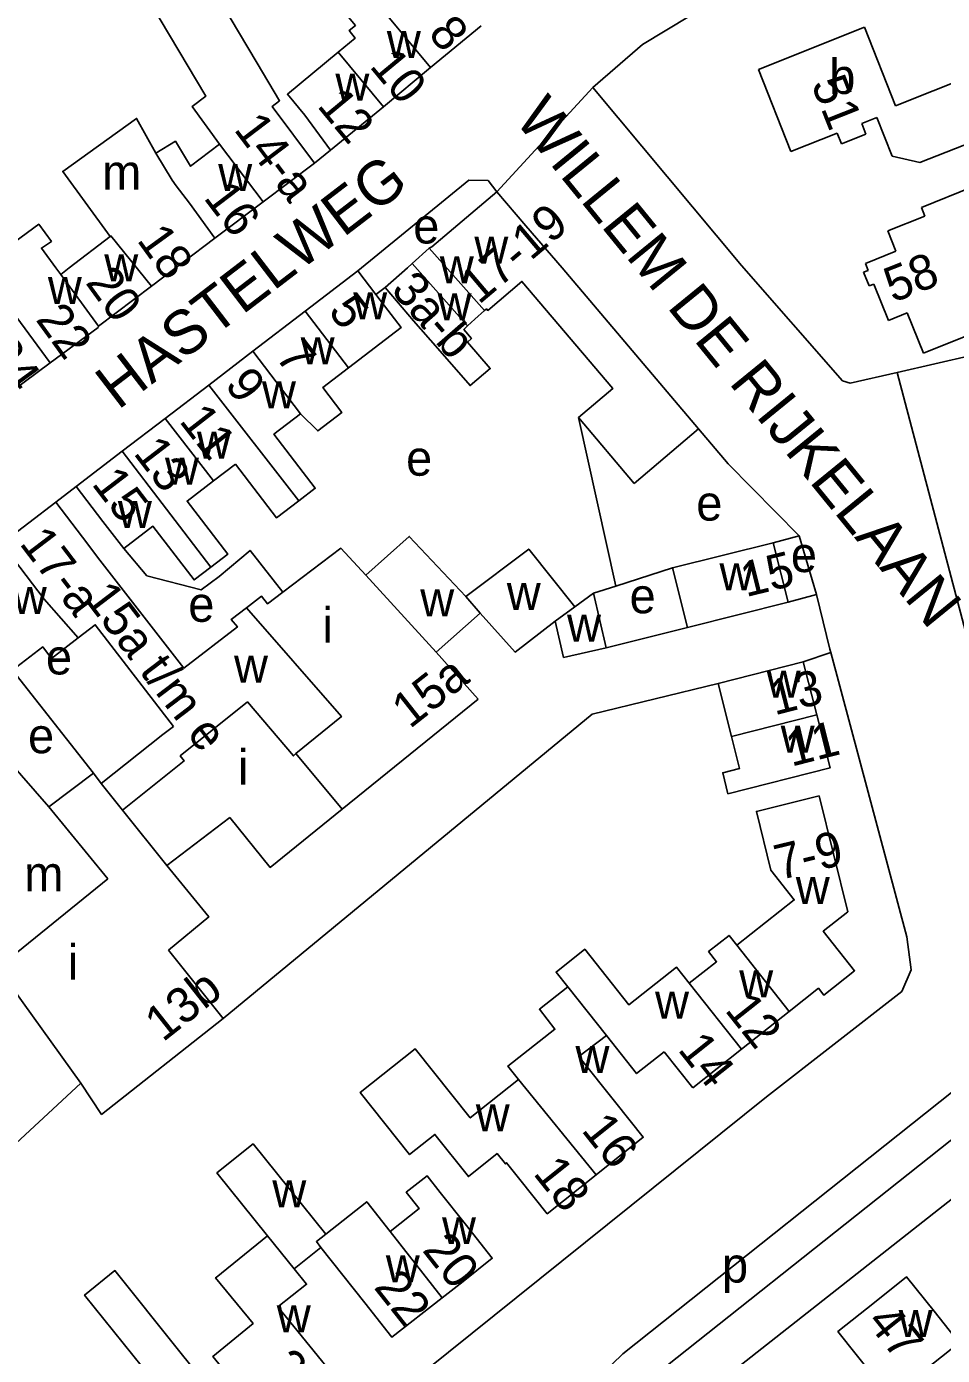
# Model space of a CAD drawing. Extents: x 159261 to 160849, y 382514 to 384534.
# Drawn here: x 159903.5 to 160007.7, y 383126.2 to 383277.5 of the extents above; entities that cross this region are included whole.
import ezdxf

# ---------------------------------------------------------------- set-up
doc = ezdxf.new("R2010")
doc.units = 0
for name, color, linetype in [('BLT_Basislijn', 7, 'Continuous'), ('BLT_Bebouwing', 7, 'Continuous'), ('BLT_Centroide', 7, 'Continuous'), ('BLT_Huisnummer', 7, 'Continuous'), ('BLT_Huisnummer_ tussenligend', 7, 'Continuous'), ('BLT_Huisnummer_reeks', 7, 'Continuous'), ('BLT_Onderdoorgang_en_onderverdeling', 7, 'Continuous'), ('BLT_Onderverdeling_panden', 7, 'Continuous'), ('BLT_Straatnaam', 7, 'Continuous'), ('BLT_Vlakafsluiter', 7, 'Continuous')]:
    doc.layers.add(name, color=color, linetype=linetype)

msp = doc.modelspace()

# ---------------------------------------------------------------- linework, layer by layer
at = {"layer": 'BLT_Basislijn'}
for p, q in [((159938.07, 383263.39), (159936.26, 383261.89)), ((159944.29, 383247.75), (159943.26, 383246.96)), ((160002.6, 383238.09), (160025.24, 383243.27)), ((159966.33, 383232.94), (159970.55, 383213.76)), ((159983.35, 383227.69), (159979.99, 383231.67)), ((159991.43, 383219.48), (159983.35, 383227.69)), ((159909.14, 383225.09), (159906.81, 383223.3)), ((159988.48, 383218.69), (159991.43, 383219.48)), ((159991.43, 383219.48), (159993.39, 383212.81)), ((159970.55, 383213.76), (159977.03, 383215.85)), ((159968.04, 383212.95), (159970.55, 383213.76)), ((159990.18, 383211.92), (159993.39, 383212.81)), ((159969.48, 383206.74), (159978.71, 383209.07)), ((159995.04, 383206.22), (159991.89, 383205.14)), ((159911.09, 383192.48), (159901.9, 383204.21)), ((159982.2, 383202.68), (159967.86, 383199.17)), ((159967.86, 383199.17), (159925.85, 383164.55))]:
    msp.add_line(p, q, dxfattribs=at)
for points in [[(160021.41, 383277.29), (160018.22, 383282.44), (159994.78, 383283.13), (159987.36, 383281.93), (159981.98, 383280.04), (159978.94, 383278.62), (159973.6, 383275.4), (159967.95, 383270.52)], [(159967.95, 383270.52), (159984.86, 383250.25), (159996.37, 383237.12), (159997.23, 383236.88), (160002.6, 383238.09)], [(159957.03, 383258.66), (159956.02, 383259.94), (159953.82, 383259.98), (159941.2, 383249.65)], [(160054.36, 383179.01), (160032.76, 383162.37), (160030.21, 383161.85), (160029.07, 383162.12), (160027.8, 383163.23), (160019.12, 383175.15), (160018.49, 383176.44), (160012.33, 383201.12), (160002.6, 383238.09)], [(159914.55, 383218.03), (159917.19, 383214.95), (159923.35, 383213.32), (159925.4, 383214.85), (159928.92, 383217.82), (159932.64, 383213.07)], [(159995.04, 383206.22), (159994.94, 383206.6), (159993.39, 383212.81)], [(159824, 383048.2), (159832.93, 383036.19), (159835.32, 383035.09), (159837.88, 383035.36), (159987.71, 383155.63), (160003.12, 383167.63), (160004.17, 383170.08), (160003.69, 383173.83), (159995.04, 383206.22)], [(159966.71, 383117.34), (159966.48, 383118.05), (159966.76, 383121.08), (159967.66, 383122.77), (159971.37, 383126.36), (160008.97, 383156.27)], [(160008.97, 383156.27), (160011.01, 383153.22), (160010.66, 383152.37), (160009.9, 383151.65), (159966.71, 383117.34)], [(160036.51, 383129.07), (160018.22, 383147.31), (160016.68, 383148.32), (160014.86, 383148.36), (160012.99, 383147.28), (159982.57, 383123.36), (159972.05, 383114.68), (159968.6, 383112.35)]]:
    msp.add_lwpolyline(points, dxfattribs=at)
at = {"layer": 'BLT_Bebouwing'}
for p, q in [((159955.25, 383277.53), (159949.46, 383272.79)), ((159986.81, 383272.58), (159998.88, 383277.37)), ((159998.88, 383277.37), (160002.41, 383268.44)), ((159949.46, 383272.79), (159944.11, 383268.3)), ((159990.5, 383263.23), (159986.81, 383272.58)), ((160002.41, 383268.44), (160010.96, 383271.83)), ((159944.11, 383268.3), (159938.07, 383263.39)), ((160000.28, 383267.11), (159998.56, 383266.43)), ((159998.56, 383266.43), (159999.04, 383265.21)), ((160002.02, 383262.71), (160000.28, 383267.11)), ((159995.77, 383265.32), (159990.5, 383263.23)), ((159996.25, 383264.11), (159995.77, 383265.32)), ((159999.04, 383265.21), (159996.25, 383264.11)), ((160013.55, 383265.3), (160005.18, 383261.99)), ((159930.43, 383257.51), (159936.26, 383261.89)), ((160005.18, 383261.99), (160002.02, 383262.71)), ((159949.63, 383252.38), (159957.03, 383258.66)), ((159957.03, 383258.66), (159960.32, 383254.78)), ((160005.35, 383256.86), (160011.26, 383259.24)), ((159924.93, 383253.37), (159930.43, 383257.51)), ((160005.73, 383255.89), (160005.35, 383256.86)), ((160001.52, 383254.19), (160005.73, 383255.89)), ((159960.32, 383254.78), (159964.46, 383250)), ((160002.45, 383251.87), (160001.52, 383254.19)), ((159913, 383253.57), (159908.34, 383249.98)), ((159917.72, 383247.9), (159924.93, 383253.37)), ((159949.32, 383252.21), (159949.63, 383252.38)), ((159947.38, 383250.48), (159949.32, 383252.21)), ((159998.99, 383250.47), (160002.45, 383251.87)), ((159907.38, 383249.23), (159906.8, 383250)), ((159908.34, 383249.98), (159907.38, 383249.23)), ((159935.21, 383245.06), (159941.2, 383249.65)), ((159941.2, 383249.65), (159943.26, 383246.96)), ((159944.29, 383247.75), (159946.83, 383250)), ((159947.38, 383250.48), (159946.83, 383250)), ((159964.46, 383250), (159979.99, 383231.67)), ((159998.75, 383249.48), (159999.3, 383249.69)), ((159999.39, 383247.93), (159998.75, 383249.48)), ((159999.3, 383249.69), (159998.99, 383250.47)), ((159917.72, 383247.9), (159911.69, 383243.35)), ((159999.92, 383248.14), (159999.39, 383247.93)), ((160001.59, 383243.99), (159999.92, 383248.14)), ((159929.24, 383240.49), (159935.21, 383245.06)), ((159954.51, 383244.14), (159955.61, 383245.12)), ((160003.74, 383244.85), (160001.59, 383243.99)), ((160005.57, 383240.28), (160003.74, 383244.85)), ((159953.67, 383243.39), (159954.51, 383244.14)), ((160011.58, 383242.67), (160005.57, 383240.28)), ((159924.23, 383236.65), (159929.24, 383240.49)), ((159906.18, 383239.17), (159899.9, 383234.52)), ((159919.25, 383232.84), (159924.23, 383236.65)), ((159914.38, 383229.11), (159919.25, 383232.84)), ((159909.14, 383225.09), (159914.38, 383229.11)), ((159924.75, 383225.74), (159927.25, 383227.65)), ((159900.65, 383218.62), (159906.81, 383223.3)), ((159988.48, 383218.69), (159977.03, 383215.85)), ((159990.18, 383211.92), (159988.48, 383218.69)), ((159977.03, 383215.85), (159978.71, 383209.07)), ((159968.04, 383212.95), (159969.48, 383206.74)), ((159978.71, 383209.07), (159990.18, 383211.92)), ((159955.13, 383210.7), (159950.12, 383206.24)), ((159950.12, 383206.24), (159954.89, 383200.88)), ((159969.48, 383206.74), (159964.61, 383205.62)), ((159982.2, 383202.68), (159991.89, 383205.14)), ((159991.89, 383205.14), (159993.43, 383199.11)), ((159919, 383196.87), (159920.2, 383197.77)), ((159906.03, 383188.63), (159911.09, 383192.48)), ((159926.64, 383187.42), (159919.45, 383181.97)), ((159919.63, 383172.32), (159925.85, 383164.55)), ((159990.3, 383165.36), (159984.87, 383161.05)), ((159984.87, 383161.05), (159979.32, 383156.66)), ((159895.84, 383144.46), (159909.68, 383157.19)), ((159937, 383138.49), (159933.93, 383136.07))]:
    msp.add_line(p, q, dxfattribs=at)
for points in [[(159936.26, 383261.89), (159931.45, 383268.36), (159932.29, 383269), (159929.73, 383273.29), (159916.39, 383295.73), (159913.84, 383300.03)], [(159907.88, 383296.49), (159910.43, 383292.19), (159923.9, 383269.54), (159922.33, 383268.34), (159925.46, 383264.06)], [(159940.92, 383286.67), (159937.99, 383284.83), (159940.32, 383280.95), (159940.69, 383280.51), (159939.39, 383279.43), (159940.91, 383277.59), (159940.2, 383276.99), (159940.9, 383276.14), (159938.95, 383274.53)], [(159938.07, 383263.39), (159935.15, 383267.37), (159933.18, 383269.74), (159938.95, 383274.53)], [(159918.2, 383263.04), (159916.01, 383267), (159911.67, 383263.89), (159907.61, 383260.97), (159913, 383253.57)], [(159925.46, 383264.06), (159922.15, 383261.55), (159920.43, 383264.39), (159918.2, 383263.04)], [(159906.8, 383250), (159905.18, 383252.23), (159906.31, 383252.99), (159904.87, 383254.95), (159898.64, 383250.39), (159902.3, 383245.4), (159901.86, 383245.07)], [(159955.61, 383245.12), (159955.84, 383245.32), (159955.98, 383245.15), (159959.88, 383248.45), (159970.22, 383236.24), (159966.33, 383232.94)], [(159943.26, 383246.96), (159944.24, 383245.68), (159946.12, 383243.18), (159940.15, 383238.61)], [(159953.67, 383243.39), (159953.28, 383242.96), (159954.13, 383241.95), (159953.68, 383241.54), (159956.26, 383238.53), (159953.97, 383236.58), (159950.31, 383240.79), (159947.54, 383243.95), (159944.29, 383247.75)], [(159911.69, 383243.35), (159911.64, 383243.21), (159906.18, 383239.17)], [(159934.68, 383233.37), (159936.63, 383231.42), (159939.39, 383233.54), (159937.22, 383236.37), (159940.15, 383238.61)], [(159934.48, 383223.48), (159936.34, 383224.9), (159931.64, 383231.04), (159934.68, 383233.37)], [(159966.33, 383232.94), (159972.66, 383225.46)], [(159972.66, 383225.46), (159976.17, 383228.44), (159979.99, 383231.67)], [(159927.25, 383227.65), (159931.94, 383221.53), (159934.48, 383223.48)], [(159914.55, 383218.03), (159912.18, 383221.12), (159909.14, 383225.09)], [(159924.47, 383215.92), (159926.39, 383217.38), (159921.75, 383223.44), (159924.75, 383225.74)], [(159906.81, 383223.3), (159909.84, 383219.33), (159911.81, 383216.73)], [(159914.55, 383218.03), (159917.87, 383220.58), (159922.56, 383214.46), (159924.47, 383215.92)], [(159942.11, 383214.99), (159947.04, 383219.41), (159953.5, 383212.59)], [(159932.64, 383213.07), (159939.27, 383218.08), (159942.11, 383214.99)], [(159953.5, 383212.59), (159960.65, 383217.97), (159965.9, 383211.4)], [(159928.51, 383211.3), (159926.78, 383209.97), (159927.49, 383209.12), (159921.39, 383204.41), (159911.81, 383216.73)], [(159928.51, 383211.3), (159930.22, 383212.62), (159930.9, 383211.75), (159932.64, 383213.07)], [(159965.9, 383211.4), (159968.04, 383212.95)], [(159963.65, 383209.76), (159959.09, 383206.26), (159955.13, 383210.7)], [(159909.34, 383207.86), (159911.3, 383209.36), (159920.2, 383197.77)], [(159964.61, 383205.62), (159963.65, 383209.76)], [(159901.9, 383204.21), (159905.33, 383206.84), (159906.33, 383205.54), (159909.34, 383207.86)], [(159983.73, 383196.65), (159982.2, 383202.68)], [(159954.89, 383200.88), (159939.41, 383188.37)], [(159983.73, 383196.65), (159984.66, 383193.01), (159982.73, 383192.52), (159983.32, 383190.12), (159994.98, 383193.08), (159993.43, 383199.11)], [(159911.99, 383191.29), (159919, 383196.87)], [(159901.35, 383194), (159906.03, 383188.63)], [(159911.09, 383192.48), (159911.99, 383191.29)], [(159990.3, 383165.36), (159993.62, 383167.99), (159994.23, 383167.22), (159997.74, 383169.99), (159994.18, 383174.48), (159996.97, 383176.69), (159993.71, 383189.89), (159988.86, 383188.69), (159986.56, 383188.12), (159988.21, 383181.42), (159990.88, 383178.05), (159984.35, 383172.88)], [(159939.41, 383188.37), (159931.22, 383181.75), (159926.64, 383187.42)], [(159919.45, 383181.97), (159924.22, 383176.11), (159919.63, 383172.32)], [(159984.35, 383172.88), (159983.46, 383174), (159981.12, 383172.16), (159982.03, 383171.01), (159978.92, 383168.55)], [(159965.11, 383168.14), (159963.76, 383169.83), (159967.03, 383172.42), (159972.05, 383166.1), (159977.47, 383170.39), (159978.92, 383168.55)], [(159965.11, 383168.14), (159961.86, 383165.59), (159963.63, 383163.33), (159958.27, 383159.13), (159959.49, 383157.61)], [(159909.68, 383157.19), (159912.02, 383153.63), (159925.85, 383164.55)], [(159968.32, 383146.75), (159973.68, 383151.03), (159970.56, 383154.94), (159966.37, 383160.21), (159969.52, 383162.6)], [(159976.07, 383160.77), (159972.93, 383158.28), (159969.52, 383162.6)], [(159968.32, 383146.75), (159962.75, 383142.32), (159959.64, 383146.23), (159958.13, 383148.12), (159957.99, 383148), (159957.05, 383149.17), (159953.78, 383146.56), (159949.96, 383151.36), (159947.08, 383149.06), (159941.46, 383156.12), (159947.71, 383161.1), (159953.99, 383153.23), (159959.49, 383157.61)], [(159979.32, 383156.66), (159976.07, 383160.77)], [(159930.93, 383139.8), (159925.16, 383146.97), (159929.27, 383150.28), (159937.55, 383140)], [(159944.88, 383140.31), (159948.17, 383142.91), (159946.7, 383144.77), (159949.08, 383146.65), (159950.58, 383144.74), (159953.4, 383141.18), (159956.5, 383137.25), (159953.17, 383134.62), (159950.79, 383132.77)], [(159937.55, 383140), (159942.21, 383143.68), (159944.88, 383140.31)], [(159932.07, 383131.72), (159935.72, 383127.24), (159938.88, 383123.38), (159932.63, 383118.27), (159929.44, 383122.18), (159927.52, 383124.53), (159926.59, 383123.77), (159924.69, 383126.09), (159929.27, 383129.83), (159925.01, 383135.04), (159925.05, 383135.07), (159930.93, 383139.8)], [(159950.79, 383132.77), (159945.08, 383128.26), (159941.98, 383132.18), (159937, 383138.49)], [(159916.89, 383112.17), (159919.71, 383108.67), (159925.93, 383113.69), (159920.63, 383120.27), (159923.9, 383122.91), (159920.78, 383126.81), (159913.55, 383135.86), (159910.08, 383133.06), (159918.9, 383122.12), (159912.82, 383117.22), (159916.89, 383112.17)], [(159933.93, 383136.07), (159935.36, 383134.3), (159932.07, 383131.72)], [(160006.79, 383131.23), (160003.67, 383135.13), (160000, 383132.22), (159995.84, 383128.91), (160000, 383123.69), (160001.81, 383121.41), (160009.66, 383127.64), (160006.79, 383131.23)]]:
    msp.add_lwpolyline(points, dxfattribs=at)
at = {"layer": 'BLT_Onderdoorgang_en_onderverdeling'}
msp.add_line((159947.38, 383250.48), (159953.67, 383243.39), dxfattribs=at)
msp.add_lwpolyline([(159955.61, 383245.12), (159949.32, 383252.21)], dxfattribs=at)
at = {"layer": 'BLT_Onderverdeling_panden'}
for p, q in [((159938.95, 383274.53), (159944.11, 383268.3)), ((159925.46, 383264.06), (159930.43, 383257.51)), ((159907.38, 383249.23), (159911.69, 383243.35)), ((159901.86, 383245.07), (159906.18, 383239.17)), ((159940.15, 383238.61), (159935.21, 383245.06)), ((159934.68, 383233.37), (159929.24, 383240.49)), ((159934.48, 383223.48), (159924.23, 383236.65)), ((159924.75, 383225.74), (159919.25, 383232.84)), ((159924.47, 383215.92), (159914.38, 383229.11)), ((159942.11, 383214.99), (159950.12, 383206.24)), ((159953.5, 383212.59), (159955.13, 383210.7)), ((159963.65, 383209.76), (159965.9, 383211.4)), ((159993.43, 383199.11), (159983.73, 383196.65)), ((159934.14, 383194.7), (159939.41, 383188.37)), ((159914.42, 383188.27), (159911.99, 383191.29)), ((159906.03, 383188.63), (159912.74, 383180.43)), ((159919.45, 383181.97), (159914.42, 383188.27)), ((159900.24, 383170.35), (159912.74, 383180.43)), ((159984.35, 383172.88), (159990.3, 383165.36)), ((159900.8, 383169.57), (159909.68, 383157.19)), ((159965.11, 383168.14), (159969.52, 383162.6)), ((159978.92, 383168.55), (159984.87, 383161.05)), ((159959.49, 383157.61), (159968.32, 383146.75)), ((159930.93, 383139.8), (159933.93, 383136.07)), ((159944.88, 383140.31), (159950.79, 383132.77))]:
    msp.add_line(p, q, dxfattribs=at)
for points in [[(159940.92, 383286.67), (159943.06, 383283.05), (159944.43, 383278.86), (159949.46, 383272.79)], [(159918.2, 383263.04), (159920.06, 383259.96), (159920.53, 383259.34)], [(159920.53, 383259.34), (159922.05, 383257.34), (159924.93, 383253.37)], [(159913, 383253.57), (159913.09, 383253.63), (159917.72, 383247.9)], [(159900.65, 383218.62), (159905.49, 383212.26), (159909.34, 383207.86)], [(159928.51, 383211.3), (159939.33, 383198.91), (159934.14, 383194.7)], [(159934.14, 383194.7), (159933.86, 383194.44), (159928.63, 383200.58), (159920.97, 383194.44), (159921.42, 383193.87), (159914.42, 383188.27)], [(159937, 383138.49), (159936.48, 383139.15), (159937.55, 383140)]]:
    msp.add_lwpolyline(points, dxfattribs=at)
at = {"layer": 'BLT_Vlakafsluiter'}
msp.add_line((159957.03, 383258.66), (159967.95, 383270.52), dxfattribs=at)

# ---------------------------------------------------------------- texts
at = {"layer": 'BLT_Centroide'}
for s, p in [('w', (159944.5, 383273.86)), ('b', (159994.86, 383269.78)), ('w', (159938.64, 383269.03)), ('m', (159912.09, 383258.88)), ('w', (159925.3, 383258.73)), ('e', (159947.5, 383252.76)), ('w', (159954.46, 383250.47)), ('w', (159912.33, 383248.45)), ('w', (159950.53, 383248.22)), ('w', (159905.91, 383245.89)), ('w', (159940.67, 383244.12)), ('w', (159950.28, 383244.02)), ('w', (159934.69, 383239.02)), ('w', (159930.28, 383234)), ('w', (159922.88, 383228.28)), ('w', (159919.24, 383225.32)), ('e', (159946.69, 383226.33)), ('e', (159979.72, 383221.22)), ('w', (159913.88, 383220.36)), ('e', (159990.49, 383215.36)), ('w', (159982.36, 383213.29)), ('w', (159901.92, 383210.59)), ('w', (159948.3, 383210.31)), ('w', (159958.15, 383211.05)), ('e', (159972.13, 383210.67)), ('e', (159921.89, 383209.7)), ('i', (159937.16, 383207.32)), ('w', (159965.01, 383207.44)), ('e', (159905.69, 383203.71)), ('w', (159927.1, 383202.78)), ('w', (159987.73, 383201.06)), ('e', (159903.65, 383194.74)), ('w', (159989.33, 383194.81)), ('i', (159927.55, 383191.16)), ('m', (159903.22, 383179.03)), ('w', (159991.05, 383177.58)), ('i', (159908.17, 383168.95)), ('w', (159984.61, 383166.95)), ('w', (159975.03, 383164.53)), ('w', (159965.97, 383158.34)), ('w', (159954.62, 383151.72)), ('w', (159931.46, 383143.05)), ('w', (159950.78, 383138.86)), ('w', (159944.38, 383134.53)), ('p', (159982.65, 383134.49)), ('w', (159931.97, 383128.81)), ('w', (160002.76, 383128.28))]:
    msp.add_text(s, height=4, dxfattribs=at).set_placement(p)
at = {"layer": 'BLT_Huisnummer'}
for s, rotation, p in [('10', 309.653, (159942.43, 383272.91)), ('51', 291.6278, (159992.77, 383270.93)), ('18', 305.9437, (159915.96, 383253.14)), ('58', 21.5725, (160002.11, 383245.98)), ('5', 307.4268, (159937.72, 383245.04)), ('24', 306.0645, (159898.57, 383240.32)), ('9', 307.4262, (159925.95, 383236.66)), ('13', 307.4434, (159915.56, 383228.88)), ('15', 307.4493, (159910.81, 383225.39)), ('15', 13.94, (159985.37, 383212.49)), ('15a', 38.2867, (159947.11, 383197.45)), ('13', 14.2419, (159988.63, 383199.04)), ('11', 14.2389, (159990.54, 383193.2)), ('13b', 38.2867, (159919, 383161.79)), ('12', 308.3737, (159982.88, 383165.48)), ('14', 308.5453, (159977.52, 383160.99)), ('16', 308.5495, (159966.55, 383151.81)), ('18', 308.5524, (159961.06, 383146.89)), ('20', 308.3131, (159948.44, 383138.16)), ('22', 308.3089, (159942.92, 383133.93)), ('47', 308.5164, (159999.01, 383129.96)), ('24', 308.3089, (159930.73, 383124.9))]:
    msp.add_text(s, height=4, rotation=rotation, dxfattribs=at).set_placement(p)
at = {"layer": 'BLT_Huisnummer_ tussenligend'}
for s, rotation, p in [('8', 309.6546, (159949.09, 383276.61)), ('12', 309.653, (159936.46, 383268.41)), ('16', 307.2038, (159923.55, 383257.95)), ('20', 305.9437, (159910.11, 383248.3)), ('22', 305.9437, (159904.44, 383244.1)), ('7', 307.4268, (159931.71, 383239.86)), ('11', 307.7989, (159920.77, 383232.54))]:
    msp.add_text(s, height=4, rotation=rotation, dxfattribs=at).set_placement(p)
at = {"layer": 'BLT_Huisnummer_reeks'}
for s, rotation, p in [('14-a', 307.2038, (159926.99, 383265.74)), ('17-19', 40.2607, (159954.97, 383245.73)), ('3a-b', 311.0411, (159944.84, 383247.39)), ('17-a', 307.2485, (159902.59, 383218.6)), ('15a t/m e', 307.2522, (159909.94, 383212.35)), ('7-9', 13.8528, (159989.19, 383180.28))]:
    msp.add_text(s, height=4, rotation=rotation, dxfattribs=at).set_placement(p)
at = {"layer": 'BLT_Straatnaam'}
for s, rotation, p in [('WILLEM DE RIJKELAAN', 309.1759, (159958.93, 383266.85)), ('HASTELWEG', 37.4482, (159913.89, 383233.74))]:
    msp.add_text(s, height=5, rotation=rotation, dxfattribs=at).set_placement(p)

doc.saveas('drawing.dxf')
